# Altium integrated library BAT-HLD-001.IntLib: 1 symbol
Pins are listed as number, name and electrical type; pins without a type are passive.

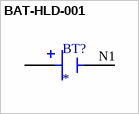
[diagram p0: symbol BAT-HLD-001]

## BAT-HLD-001
designator BT?
Battery Retainer Coin, 20.0mm 1 Cell SMD (SMT) Tab; MP: BAT-HLD-001
footprint BAT_BAT-HLD-001
pins: N1 NEG, P1 POS, P2 POS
